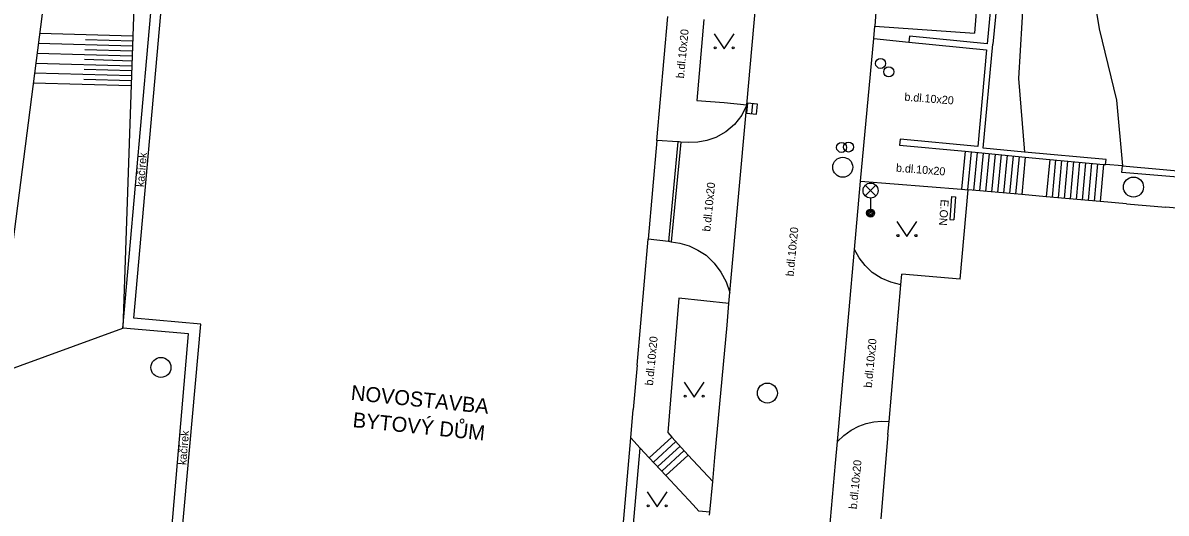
# Model space of a CAD drawing. Extents: x -598233 to -596890, y -1157848 to -1156431.
# Drawn here: x -598000.2 to -597943.1, y -1156933.2 to -1156908.6 of the extents above; entities that cross this region are included whole.
import ezdxf

# ---------------------------------------------------------------- set-up
doc = ezdxf.new("R2010")
doc.units = 0
for name, color, linetype in [('Level 10', 7, 'Continuous'), ('Level 11', 7, 'Continuous'), ('Level 14', 7, 'Continuous'), ('Level 15', 7, 'Continuous'), ('Level 24', 7, 'Continuous'), ('Level 27', 7, 'Continuous'), ('Level 28', 7, 'Continuous'), ('Level 33', 7, 'Continuous'), ('Level 36', 7, 'Continuous'), ('Level 40', 7, 'Continuous'), ('Level 41', 7, 'Continuous'), ('Level 5', 7, 'Continuous'), ('Level 6', 7, 'Continuous'), ('Level 7', 7, 'Continuous')]:
    doc.layers.add(name, color=color, linetype=linetype)

msp = doc.modelspace()

# ---------------------------------------------------------------- linework, layer by layer
at = {"layer": 'Level 10'}
for points in [[(-597952.45, -1156906.32), (-597952.45, -1156906.37), (-597952.67, -1156909.15)], [(-597964.04, -1156912.74), (-597963.52, -1156906.75)], [(-597957.7, -1156909.43), (-597957.65, -1156908.8)], [(-597957.65, -1156908.8), (-597952.67, -1156909.15)], [(-597958.36, -1156916.55), (-597957.7, -1156909.43)], [(-597964.04, -1156912.74), (-597964.3, -1156913.26), (-597964.66, -1156913.72), (-597965.1, -1156914.09), (-597965.6, -1156914.38)], [(-597965.6, -1156914.38), (-597966.04, -1156914.52), (-597966.5, -1156914.61), (-597966.96, -1156914.63), (-597967.35, -1156914.6), (-597967.42, -1156914.59)], [(-597967.42, -1156914.59), (-597967.49, -1156914.59), (-597968.54, -1156914.52)], [(-597958.67, -1156919.97), (-597958.36, -1156916.55)], [(-597967.89, -1156919.58), (-597967.96, -1156919.57), (-597968.97, -1156919.45)], [(-597967.89, -1156919.58), (-597967.82, -1156919.59), (-597967.4, -1156919.65), (-597966.93, -1156919.79), (-597966.49, -1156920), (-597966.07, -1156920.26)], [(-597957.78, -1156921.12), (-597958.13, -1156920.78), (-597958.43, -1156920.39), (-597958.67, -1156919.97)], [(-597966.07, -1156920.26), (-597965.67, -1156920.65), (-597965.34, -1156921.1), (-597965.08, -1156921.59), (-597964.89, -1156922.12)], [(-597956.34, -1156921.74), (-597956.85, -1156921.61), (-597957.33, -1156921.4), (-597957.78, -1156921.12)], [(-597964.94, -1156922.67), (-597964.89, -1156922.12)], [(-597965.02, -1156923.75), (-597964.94, -1156922.67)], [(-597965.65, -1156930.37), (-597965.02, -1156923.75)], [(-597958.44, -1156928.8), (-597958.08, -1156928.67), (-597957.7, -1156928.59), (-597957.32, -1156928.56), (-597956.93, -1156928.58)], [(-597959.52, -1156929.58), (-597959.2, -1156929.27), (-597958.83, -1156929.01), (-597958.44, -1156928.8)], [(-597959.61, -1156930.66), (-597959.52, -1156929.58)], [(-597965.75, -1156931.58), (-597965.65, -1156930.37)], [(-597959.97, -1156934.63), (-597959.61, -1156930.66)], [(-597965.91, -1156933.26), (-597965.9, -1156933.11), (-597965.75, -1156931.58)]]:
    msp.add_lwpolyline(points, dxfattribs=at)
at = {"layer": 'Level 11'}
for points in [[(-597951.63, -1156905.39), (-597952.04, -1156909.69)], [(-597995.24, -1156923.9), (-597993.66, -1156906.05)], [(-597957.44, -1156905.93), (-597957.44, -1156905.98), (-597957.65, -1156908.8)], [(-597966.2, -1156908.47), (-597966.55, -1156912.52)], [(-597955.92, -1156909.3), (-597955.95, -1156909.6)], [(-597952.04, -1156909.69), (-597955.92, -1156909.3)], [(-597957.7, -1156909.43), (-597955.95, -1156909.6)], [(-597955.95, -1156909.6), (-597952.07, -1156909.99)], [(-597952.07, -1156909.99), (-597952.5, -1156914.82)], [(-597966.55, -1156912.52), (-597965.18, -1156912.63)], [(-597965.18, -1156912.63), (-597964.04, -1156912.74)], [(-597964.89, -1156922.12), (-597964.04, -1156912.74)], [(-597956.38, -1156914.45), (-597956.41, -1156914.75)], [(-597952.5, -1156914.82), (-597956.38, -1156914.45)], [(-597956.41, -1156914.75), (-597953.13, -1156915.06), (-597950.13, -1156915.35), (-597948.9, -1156915.47), (-597946.22, -1156915.72), (-597946.12, -1156915.73)], [(-597953.13, -1156915.06), (-597953.31, -1156916.96)], [(-597952.83, -1156915.09), (-597953.01, -1156916.99)], [(-597952.53, -1156915.12), (-597952.71, -1156917.02)], [(-597952.23, -1156915.15), (-597952.41, -1156917.04)], [(-597951.94, -1156915.18), (-597952.12, -1156917.07)], [(-597951.64, -1156915.2), (-597951.82, -1156917.1)], [(-597951.34, -1156915.23), (-597951.52, -1156917.12)], [(-597951.04, -1156915.26), (-597951.22, -1156917.15)], [(-597950.74, -1156915.29), (-597950.92, -1156917.18)], [(-597950.44, -1156915.32), (-597950.62, -1156917.21)], [(-597950.13, -1156915.35), (-597950.3, -1156917.23)], [(-597948.9, -1156915.47), (-597949.08, -1156917.34)], [(-597948.61, -1156915.49), (-597948.78, -1156917.36)], [(-597948.31, -1156915.52), (-597948.48, -1156917.39)], [(-597948.01, -1156915.55), (-597948.19, -1156917.42)], [(-597947.71, -1156915.58), (-597947.89, -1156917.44)], [(-597947.41, -1156915.61), (-597947.59, -1156917.47)], [(-597947.11, -1156915.64), (-597947.29, -1156917.5)], [(-597946.81, -1156915.66), (-597946.99, -1156917.52)], [(-597946.51, -1156915.69), (-597946.69, -1156917.55)], [(-597946.22, -1156915.72), (-597946.39, -1156917.57)], [(-597945.26, -1156915.79), (-597946.12, -1156915.73)], [(-597945.3, -1156916.12), (-597945.26, -1156915.79)], [(-597925.55, -1156917.78), (-597945.3, -1156916.12)], [(-597958.36, -1156916.55), (-597953.31, -1156916.96), (-597952.99, -1156916.99)], [(-597959.52, -1156929.58), (-597958.67, -1156919.97)], [(-597967.45, -1156922.4), (-597967.73, -1156925.85)], [(-597964.94, -1156922.67), (-597967.45, -1156922.4)], [(-598001.6, -1156926.23), (-597995.24, -1156923.9)], [(-597991.95, -1156924.19), (-597995.24, -1156923.9)], [(-597992.96, -1156935.89), (-597991.95, -1156924.19)], [(-597967.73, -1156925.85), (-597968, -1156929.13)], [(-597968, -1156929.13), (-597967.79, -1156929.35), (-597966.97, -1156930.25), (-597965.75, -1156931.58)], [(-597966.73, -1156932.74), (-597968.09, -1156931.28), (-597968.92, -1156930.39), (-597969.37, -1156929.9), (-597969.84, -1156929.39)], [(-597968.92, -1156930.39), (-597967.79, -1156929.35)], [(-597968.71, -1156930.61), (-597967.59, -1156929.58)], [(-597968.5, -1156930.83), (-597967.38, -1156929.8)], [(-597970.07, -1156937.88), (-597969.37, -1156929.9)], [(-597968.3, -1156931.05), (-597967.18, -1156930.03)], [(-597968.09, -1156931.28), (-597966.97, -1156930.25)], [(-597966.45, -1156933.06), (-597966.73, -1156932.74)], [(-597965.9, -1156933.11), (-597966.45, -1156933.06)]]:
    msp.add_lwpolyline(points, dxfattribs=at)
at = {"layer": 'Level 14'}
for points in [[(-597986.74, -1156881.03), (-597982.74, -1156881.52), (-597973.41, -1156882), (-597969.54, -1156882.46), (-597964.54, -1156883.71), (-597962.03, -1156885.09), (-597958.89, -1156886.84), (-597956.73, -1156888.67), (-597956.22, -1156888.79), (-597954.06, -1156891.32), (-597951.77, -1156894.98), (-597950.79, -1156898.51), (-597950.25, -1156902.48), (-597950.14, -1156905.8), (-597950.47, -1156911.42), (-597950.16, -1156915.1)], [(-597947.23, -1156904), (-597946.44, -1156908.94)], [(-597994.6, -1156905.41), (-597995.24, -1156923.9)], [(-597999.04, -1156906.35), (-598001.6, -1156926.23)], [(-597946.44, -1156908.94), (-597945.56, -1156912.51), (-597945.26, -1156915.79)]]:
    msp.add_lwpolyline(points, dxfattribs=at)
at = {"layer": 'Level 15'}
for points in [[(-597994.73, -1156909.3), (-597999.4, -1156909.18)], [(-597994.75, -1156909.8), (-597999.47, -1156909.68)], [(-597994.74, -1156909.55), (-597997.11, -1156909.49)], [(-597994.77, -1156910.3), (-597999.53, -1156910.17)], [(-597994.76, -1156910.05), (-597997.13, -1156909.99)], [(-597994.79, -1156910.8), (-597999.6, -1156910.67)], [(-597994.8, -1156911.04), (-597997.17, -1156910.98)], [(-597994.78, -1156910.55), (-597997.15, -1156910.48)], [(-597994.8, -1156911.29), (-597999.66, -1156911.16)], [(-597994.81, -1156911.54), (-597997.19, -1156911.48)], [(-597994.82, -1156911.79), (-597999.72, -1156911.66)]]:
    msp.add_lwpolyline(points, dxfattribs=at)
at = {"layer": 'Level 24'}
for points in [[(-597967.49, -1156914.59), (-597967.96, -1156919.57)], [(-597967.35, -1156914.6), (-597967.82, -1156919.59)], [(-597953.82, -1156917.33), (-597953.9, -1156918.48)], [(-597953.82, -1156917.33), (-597953.62, -1156917.34)], [(-597953.62, -1156917.34), (-597953.7, -1156918.49)], [(-597953.9, -1156918.48), (-597953.7, -1156918.49)]]:
    msp.add_lwpolyline(points, dxfattribs=at)
at = {"layer": 'Level 27'}
msp.add_line((-597963.7672, -1156912.681), (-597963.8128, -1156913.179), dxfattribs=at)
msp.add_lwpolyline([(-597964.0162, -1156912.6583), (-597964.0617, -1156913.1562), (-597963.5638, -1156913.2017), (-597963.5183, -1156912.7038)], close=True, dxfattribs=at)
for centre in [(-597959.25, -1156915.86), (-597944.72, -1156916.85), (-597993.33, -1156925.87), (-597963.02, -1156927.15)]:
    msp.add_circle(centre, 0.5, dxfattribs=at)
at = {"layer": 'Level 28'}
for centre in [(-597957.36, -1156910.67), (-597956.95, -1156911.09), (-597959.31, -1156914.87), (-597958.96, -1156914.85)]:
    msp.add_circle(centre, 0.25, dxfattribs=at)
at = {"layer": 'Level 33'}
for p, q in [((-597958.125, -1156917.29), (-597957.595, -1156916.76)), ((-597958.125, -1156916.76), (-597957.595, -1156917.29)), ((-597957.86, -1156917.4), (-597957.86, -1156918.15))]:
    msp.add_line(p, q, dxfattribs=at)
for centre, radius in [((-597957.86, -1156917.025), 0.375), ((-597957.86, -1156918.15), 0.2), ((-597957.86, -1156918.15), 0.1445), ((-597957.86, -1156918.15), 0.0876)]:
    msp.add_circle(centre, radius, dxfattribs=at)
at = {"layer": 'Level 36'}
for points in [[(-597965.68, -1156909.19), (-597965.18, -1156909.94), (-597964.68, -1156909.19)], [(-597956.54, -1156918.58), (-597956.04, -1156919.33), (-597955.54, -1156918.58)], [(-597967.18, -1156926.6), (-597966.68, -1156927.35), (-597966.18, -1156926.6)], [(-597969.03, -1156932.09), (-597968.53, -1156932.84), (-597968.03, -1156932.09)]]:
    msp.add_lwpolyline(points, dxfattribs=at)
for centre in [(-597965.6302, -1156909.8898), (-597964.7308, -1156909.8898), (-597956.4902, -1156919.2798), (-597955.5908, -1156919.2798), (-597967.1302, -1156927.2998), (-597966.2308, -1156927.2998), (-597968.9802, -1156932.7898), (-597968.0808, -1156932.7898)]:
    msp.add_circle(centre, 0.05, dxfattribs=at)
at = {"layer": 'Level 5'}
for points in [[(-597994.69, -1156923.41), (-597993.15, -1156906.1)], [(-597968.54, -1156914.52), (-597968, -1156908.33)], [(-597968.54, -1156914.52), (-597968.97, -1156919.45)], [(-597953.38, -1156921.45), (-597952.99, -1156916.99)], [(-597945.07, -1156917.69), (-597946.39, -1156917.57), (-597949.08, -1156917.34), (-597950.3, -1156917.23), (-597952.99, -1156916.99)], [(-597945.07, -1156917.69), (-597943.1, -1156917.86)], [(-597938.62, -1156918.26), (-597943.1, -1156917.86)], [(-597969.52, -1156925.76), (-597968.97, -1156919.45)], [(-597956.34, -1156921.74), (-597956.29, -1156921.2)], [(-597953.38, -1156921.45), (-597956.29, -1156921.2)], [(-597956.93, -1156928.58), (-597956.34, -1156921.74)], [(-597991.34, -1156923.71), (-597994.69, -1156923.41)], [(-597992.43, -1156935.94), (-597991.34, -1156923.71)], [(-597969.52, -1156925.76), (-597969.72, -1156927.97)], [(-597970.58, -1156937.84), (-597969.84, -1156929.39), (-597969.72, -1156927.97)], [(-597956.99, -1156929.23), (-597956.93, -1156928.58)], [(-597956.99, -1156929.23), (-597957.35, -1156933.44)]]:
    msp.add_lwpolyline(points, dxfattribs=at)
at = {"layer": 'Level 6'}
for points in [[(-597968.54, -1156914.52), (-597968.97, -1156919.45)], [(-597945.07, -1156917.69), (-597943.1, -1156917.86)], [(-597956.93, -1156928.58), (-597956.34, -1156921.74)], [(-597969.52, -1156925.76), (-597969.72, -1156927.97)], [(-597956.99, -1156929.23), (-597957.35, -1156933.44)]]:
    msp.add_lwpolyline(points, dxfattribs=at)
at = {"layer": 'Level 7'}
for points in [[(-597951.33, -1156905.42), (-597951.75, -1156909.7)], [(-597952.24, -1156914.9), (-597951.75, -1156909.7)], [(-597946.09, -1156915.48), (-597950.16, -1156915.1), (-597952.24, -1156914.9)], [(-597946.12, -1156915.73), (-597946.09, -1156915.48)], [(-597945.26, -1156915.79), (-597925.5, -1156917.57), (-597907.31, -1156919.31)]]:
    msp.add_lwpolyline(points, dxfattribs=at)

# ---------------------------------------------------------------- texts
at = {"layer": 'Level 40'}
for s, rotation, p in [('b.dl.10x20', 84.36317, (-597967.19, -1156911.43)), ('b.dl.10x20', 355.56922, (-597956.18, -1156912.53)), ('kačírek', 85.06615, (-597994.18, -1156916.86)), ('b.dl.10x20', 355.56922, (-597956.6, -1156916.08)), ('b.dl.10x20', 84.36317, (-597965.87, -1156919.09)), ('b.dl.10x20', 84.36317, (-597961.71, -1156921.33)), ('b.dl.10x20', 84.36317, (-597968.74, -1156926.79)), ('b.dl.10x20', 84.36317, (-597957.8, -1156926.9)), ('kačírek', 85.06615, (-597992.07, -1156930.76)), ('b.dl.10x20', 84.36317, (-597958.55, -1156932.97))]:
    msp.add_text(s, height=0.4, rotation=rotation, dxfattribs=at).set_placement(p)
at = {"layer": 'Level 41'}
for s, height, rotation, p in [('E.ON', 0.4, 266, (-597954.35, -1156917.46)), ('NOVOSTAVBA', 0.75, 354.16386, (-597983.86, -1156927.49)), ('BYTOVÝ DŮM', 0.75, 354.16183, (-597983.77, -1156928.85))]:
    msp.add_text(s, height=height, rotation=rotation, dxfattribs=at).set_placement(p)

doc.saveas('drawing.dxf')
